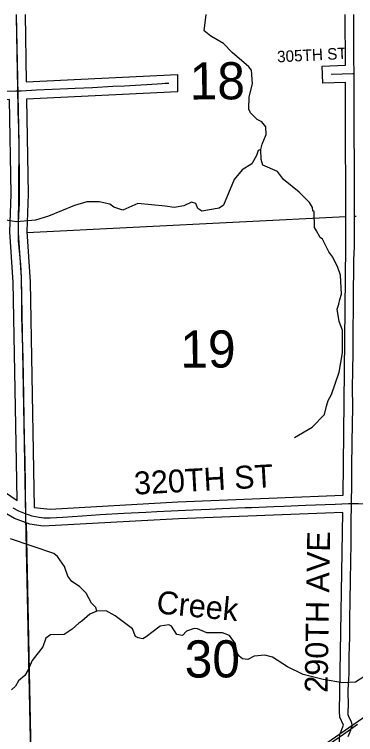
# Model space of a CAD drawing. Extents: x 10133 to 81668, y 7924 to 11018.
# Drawn here: x 11275.1 to 11454.1, y 9217.2 to 9594.9 of the extents above; entities that cross this region are included whole.
import ezdxf

# ---------------------------------------------------------------- set-up
doc = ezdxf.new("R2010")
doc.units = 0
for name, color, linetype in [('tdCoCityStreetMajor', 7, 'Continuous'), ('tdCoCityStreetMinor', 7, 'Continuous'), ('tdCoCorpTxt', 7, 'Continuous'), ('tdCoHydroRiver', 7, 'Continuous'), ('tdCoPriNonDiv', 7, 'Continuous'), ('tdCoRRCL', 7, 'Continuous'), ('tdCoRROwnerTxt', 7, 'Continuous'), ('tdCoShieldStRte', 7, 'Continuous'), ('tdCoStrucNonDivPri', 7, 'Continuous'), ('tdCoSurfGravelUnbanded', 7, 'Continuous'), ('tdCoTwpNameTxt', 7, 'Continuous')]:
    doc.layers.add(name, color=color, linetype=linetype)

msp = doc.modelspace()

# ---------------------------------------------------------------- linework, layer by layer
at = {"layer": 'tdCoCityStreetMajor'}
msp.add_lwpolyline([(11450.18, 9216.24), (11450.65, 9217.4), (11451.54, 9219.52), (11451.98, 9220.86), (11452.23, 9221.67), (11452.25, 9222.29), (11452.05, 9223.2), (11451.86, 9223.74), (11450.52, 9226.65), (11450.23, 9227.49), (11450.15, 9229.41), (11450.28, 9232.42), (11450.18, 9240.02), (11450.4, 9243.99), (11450.65, 9248.92), (11450.8, 9257.28), (11450.94, 9264.41), (11450.99, 9267.47), (11451.04, 9277.53), (11451.24, 9287.34), (11451.46, 9297.97), (11451.56, 9308.18), (11451.73, 9317.16), (11451.78, 9320.02), (11451.78, 9328.89), (11452, 9337.45), (11452, 9338.42)], dxfattribs=at)
at = {"layer": 'tdCoCityStreetMinor'}
for points in [[(11276.91, 9554.82), (11276.83, 9556.92), (11276.71, 9564.49), (11276.53, 9575), (11276.26, 9583.8), (11276.11, 9593.96), (11276.1, 9594.91)], [(11453.32, 9563.98), (11453.16, 9571.58), (11453.16, 9575.67), (11453.14, 9582.58), (11453.19, 9584.77), (11453.16, 9594.47), (11453.16, 9594.91)], [(11441.21, 9563.48), (11447.12, 9563.7), (11452.62, 9563.93), (11453.32, 9563.98)], [(11453.46, 9489.11), (11453.48, 9494.05), (11453.56, 9506.08), (11453.46, 9515.38), (11453.43, 9518.83), (11453.41, 9530.18), (11453.41, 9532.17), (11453.38, 9543.59), (11453.34, 9555.21), (11453.34, 9563.05), (11453.32, 9563.98)], [(11276.91, 9554.82), (11278.68, 9554.87), (11286.67, 9555.26), (11303.02, 9555.98), (11306.99, 9556.28), (11315.99, 9556.65), (11326.77, 9557.19), (11332.79, 9557.36), (11341.37, 9557.9), (11344.62, 9558.15), (11352.52, 9558.69), (11354.17, 9558.84), (11356.07, 9558.84)], [(11164.7, 9552.62), (11166.32, 9552.66), (11173.1, 9552.73), (11180.83, 9552.85), (11188.82, 9552.97), (11201.49, 9553.27), (11208.55, 9553.39), (11222.38, 9553.66), (11227.56, 9553.78), (11240.68, 9554.03), (11248.18, 9554.18), (11260.04, 9554.4), (11266.08, 9554.52), (11275.82, 9554.8), (11276.91, 9554.82)], [(11281, 9333.05), (11281.01, 9334.98), (11280.96, 9343.71), (11280.85, 9348.42), (11280.68, 9360.43), (11280.45, 9372.26), (11280.18, 9383.04), (11280.01, 9394.7), (11279.84, 9404.89), (11279.64, 9414.68), (11279.39, 9425.26), (11278.95, 9436.36), (11278.98, 9446.98), (11278.85, 9454.51), (11278.78, 9456.55), (11278.63, 9460.62), (11278.41, 9463.8), (11278.09, 9467.18), (11277.64, 9472.68), (11277.3, 9476.08), (11277.27, 9477.17), (11277.15, 9480.97), (11277.25, 9485.31), (11277.4, 9489.38), (11277.69, 9495.99), (11277.79, 9500.65), (11277.72, 9511.45), (11277.62, 9521.76), (11277.59, 9524.22), (11277.4, 9535.64), (11277.13, 9543.85), (11277.03, 9547.23), (11276.95, 9553.81), (11276.91, 9554.82)], [(11452, 9338.42), (11452, 9339.28), (11452.03, 9347.83), (11452.18, 9357.55), (11452.3, 9370.42), (11452.4, 9379.97), (11452.57, 9388.84), (11452.45, 9399.15), (11452.6, 9408.01), (11452.74, 9417.55), (11452.84, 9429.95), (11452.94, 9440.19), (11452.97, 9447.29), (11453.06, 9450.55), (11453.19, 9460.16), (11453.16, 9466.08), (11453.43, 9473.16), (11453.43, 9482.58), (11453.46, 9489.11)], [(11453.46, 9489.11), (11454.39, 9489.13)], [(11281, 9333.05), (11282.31, 9332.6), (11284.21, 9331.99), (11287.99, 9331.27), (11290.55, 9330.95), (11293.9, 9330.88), (11300.49, 9331.2), (11310.67, 9331.94), (11320.07, 9332.63), (11332.4, 9333.34), (11343.97, 9333.91), (11349.74, 9334.23), (11361.05, 9334.8), (11368.7, 9335.04), (11377.36, 9335.41), (11384.01, 9335.78), (11396.22, 9336.3), (11399.5, 9336.35), (11411.21, 9336.74), (11416.49, 9336.94), (11427.74, 9337.51), (11443.37, 9338.1), (11450.43, 9338.37), (11452, 9338.42)], [(11452, 9338.42), (11453.11, 9338.45), (11455.63, 9338.35), (11459.28, 9338.15), (11461.35, 9337.93), (11462.83, 9337.66), (11466.38, 9336.94), (11474.59, 9334.7), (11477.58, 9333.88), (11486.9, 9331.44), (11491.63, 9330.18), (11499.18, 9328.16), (11503.03, 9327.1), (11515.95, 9323.85), (11521.99, 9322.24), (11531.48, 9319.85), (11537.21, 9318.62), (11545.25, 9317.04), (11548.45, 9316.33), (11550.92, 9315.68), (11553.41, 9314.77)], [(11274.26, 9336.06), (11277.26, 9334.49), (11279.78, 9333.43), (11281, 9333.05)]]:
    msp.add_lwpolyline(points, dxfattribs=at)
at = {"layer": 'tdCoHydroRiver'}
for points in [[(11404.41, 9524.03), (11405.07, 9526.88), (11407.12, 9531.89), (11407.05, 9535.91), (11404.88, 9538.48), (11402.49, 9539.86), (11398.88, 9543.35), (11398.13, 9545.23), (11398.26, 9551.63), (11400.04, 9558.53), (11399.45, 9565.62), (11398, 9567.49), (11389.35, 9574.92), (11384.77, 9579.58), (11378.08, 9583.49), (11374.71, 9586.28), (11375.73, 9594.91)], [(11404.41, 9524.03), (11403, 9523.53), (11402.09, 9520.91), (11399.56, 9516.6), (11394.64, 9513.44), (11390.46, 9508.4), (11384.77, 9494.81), (11382.43, 9493.35), (11373.46, 9491.78), (11371.3, 9493.16), (11370.31, 9495.75), (11367.93, 9496.42), (11363.94, 9494.46), (11358.98, 9493.66), (11354.23, 9494.3), (11339.77, 9495.71), (11332.01, 9492.27), (11327.25, 9493.84), (11325.09, 9495.46), (11319.63, 9496.56), (11312.99, 9496.68), (11306.63, 9494.68), (11293, 9489.01), (11286.16, 9487), (11276.23, 9486.12), (11269.35, 9487.19)], [(11422.1, 9373.01), (11431.24, 9378.37), (11437.76, 9385.11), (11438.87, 9389.4), (11439.77, 9392.49), (11441.37, 9395.59), (11445.44, 9407.27), (11447.16, 9417.48), (11447.2, 9429.32), (11445.47, 9433.79), (11444.41, 9440.4), (11445.31, 9443.02), (11445.75, 9445.39), (11446.65, 9448.25), (11446.24, 9458.19), (11444.75, 9462.19), (11442.06, 9467.59), (11440.12, 9470.4), (11436.69, 9476.97), (11435.49, 9477.9), (11433.54, 9481.42), (11432.57, 9483.06), (11432.43, 9491.35), (11431.71, 9491.81), (11431.44, 9493.7), (11429.98, 9496.28), (11424.44, 9501.63), (11416.27, 9508.36), (11413.13, 9512.57), (11405.5, 9515.76), (11404.5, 9518.82), (11404.41, 9524.03)], [(11318.25, 9282), (11317.75, 9283.88), (11315.58, 9286.21), (11312.65, 9291.37), (11309.28, 9294.87), (11305.21, 9297.41), (11303.03, 9300.21), (11301.29, 9305.39), (11297.65, 9310.54), (11295.73, 9312.17), (11273.1, 9319.84)], [(11318.25, 9282), (11314.73, 9280.28), (11310.53, 9276.66), (11308.89, 9275.68), (11305.39, 9272.55), (11301.18, 9269.63), (11294.07, 9269.51), (11291.5, 9267.81), (11289.92, 9263.29), (11284.35, 9256.09), (11282.31, 9251.08), (11280.46, 9248.21), (11277.2, 9245.31), (11275.58, 9242.68), (11273.48, 9240.75)], [(11459.01, 9247.89), (11454.09, 9244.73), (11447.46, 9244.38), (11437.02, 9246.1), (11426.55, 9248.77), (11418.44, 9252.66), (11410.54, 9257.74), (11406.49, 9258.85), (11400.82, 9258.28), (11397.53, 9256.57), (11394.68, 9257), (11393, 9258.39), (11391.78, 9260.5), (11391, 9264.75), (11387.85, 9269.19), (11384.27, 9270.55), (11375.98, 9270.65), (11371.21, 9272.7), (11369.32, 9272.91), (11365.32, 9271.42), (11363.22, 9269.25), (11360.37, 9269.68), (11357.46, 9274.13), (11356.03, 9274.82), (11351.54, 9274.03), (11344.29, 9268.46), (11342.41, 9267.48), (11340.04, 9267.92), (11338.61, 9268.6), (11337.12, 9272.6), (11328, 9279.56), (11323.23, 9282.08), (11318.25, 9282)]]:
    msp.add_lwpolyline(points, dxfattribs=at)
at = {"layer": 'tdCoPriNonDiv'}
for points in [[(11280.65, 9594.91), (11281.29, 9559.5), (11360.56, 9563.34), (11360.57, 9554.34), (11281.49, 9550.5), (11282.29, 9500.68), (11281.65, 9480.99), (11283.35, 9454.67), (11285.5, 9336.32), (11293.84, 9335.38)], [(11293.84, 9335.38), (11360.83, 9339.29), (11447.52, 9342.76), (11448.94, 9473.25), (11448.84, 9559.27), (11436.88, 9558.82), (11436.54, 9567.81), (11448.73, 9568.27), (11448.61, 9594.91)], [(11276.48, 9339.98), (11276.18, 9360.35), (11274.35, 9454.39), (11272.65, 9480.82), (11273.29, 9500.68), (11272.49, 9550.2), (11169.45, 9548.19), (11170.33, 9483.05), (11171.63, 9438.35), (11171.44, 9410.46), (11172.19, 9360.44), (11234.14, 9360.66), (11241.18, 9360.03), (11247.21, 9358.37), (11253.67, 9355.53), (11276.48, 9339.98)], [(11445.46, 9211.77), (11445.79, 9217.23), (11447.66, 9222.11), (11445.89, 9226.32), (11445.66, 9229.24), (11447.41, 9333.75), (11361.24, 9330.3), (11290.22, 9326.46), (11283.1, 9327.63), (11275.18, 9330.5), (11269.68, 9333.64), (11249.37, 9347.62), (11239.62, 9351.16), (11222.85, 9351.69), (11156.16, 9351.27), (11149.17, 9351.99), (11146.98, 9350.43), (11144.45, 9349.63), (11134.95, 9348.96), (11135.06, 9321.32), (11136.39, 9236.77), (11139.85, 9108.74)]]:
    msp.add_lwpolyline(points, dxfattribs=at)
at = {"layer": 'tdCoRRCL'}
for points in [[(11408.96, 9192.14), (11496.88, 9252.86), (11521.5, 9269.09), (11537.38, 9279.92), (11549.05, 9286.44), (11568.06, 9294.84)], [(11440.47, 9212.33), (11447.66, 9217.37), (11455.03, 9222.58)]]:
    msp.add_lwpolyline(points, dxfattribs=at)
at = {"layer": 'tdCoStrucNonDivPri'}
for points in [[(11281.67, 9480.49), (11448.97, 9488.88)], [(11281.2, 9328.24), (11284.23, 9181.46)]]:
    msp.add_lwpolyline(points, dxfattribs=at)
at = {"layer": 'tdCoSurfGravelUnbanded'}
msp.add_lwpolyline([(11281.2, 9328.24), (11284.23, 9181.46), (11285.76, 9111.23)], dxfattribs=at)
at = {"layer": 'tdCoTwpNameTxt'}
msp.add_lwpolyline([(11287.47, 9032.68), (11284.23, 9181.46), (11281.14, 9331.19), (11278.77, 9457.01), (11277.18, 9480.27), (11277.53, 9527.34), (11276.22, 9594.91)], dxfattribs=at)

# ---------------------------------------------------------------- texts
at = {"layer": 'tdCoCorpTxt'}
msp.add_text('Creek', height=12, rotation=354.4584, dxfattribs=at).set_placement((11349.28, 9280.81))
at = {"layer": 'tdCoRROwnerTxt'}
for s, rotation, p in [('18', 0.2273, (11367.06, 9550.26)), ('19', 0.2274, (11362.16, 9409.6)), ('30', 0.2274, (11364.46, 9247.09))]:
    msp.add_text(s, height=19.5, rotation=rotation, dxfattribs=at).set_placement(p)
at = {"layer": 'tdCoShieldStRte'}
for s, height, rotation, p in [('305TH ST', 6, 2.9624, (11413.05, 9569.71)), ('320TH ST', 12, 3.1691, (11338.13, 9343)), ('290TH AVE', 12, 89.0656, (11439.36, 9239.04))]:
    msp.add_text(s, height=height, rotation=rotation, dxfattribs=at).set_placement(p)

doc.saveas('drawing.dxf')
